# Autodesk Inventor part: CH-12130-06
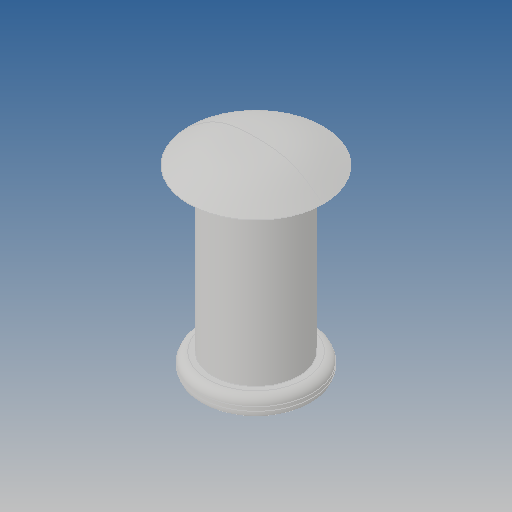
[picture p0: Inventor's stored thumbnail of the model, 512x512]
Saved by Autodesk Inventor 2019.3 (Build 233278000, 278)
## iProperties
Created: 2017-11
Part Number: CH-12130-06
Material: Ogólny
Document SubType Name: Modeling
Designer: Admin
Density: 1 g/cm^3
Appearance: Domyślna
Author: Admin
Revision Number: ÈÎºÎ
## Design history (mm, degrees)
feature "Ô²½Ç3"
node "Bryła1"
